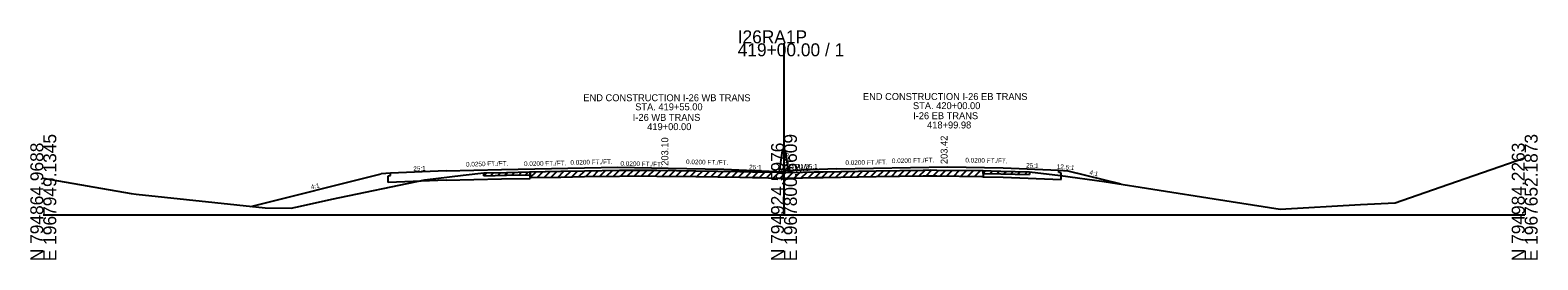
# Model space of a CAD drawing. Extents: x -44 to 4323, y -10 to 9601.
# Drawn here: x 997.2 to 1322.8, y 1490.3 to 1539.9 of the extents above; entities that cross this region are included whole.
import ezdxf

# ---------------------------------------------------------------- set-up
doc = ezdxf.new("R2010")
doc.units = 0
for name, color, linetype in [('1', 7, 'Continuous'), ('DateStamp', 7, 'Continuous'), ('NotForConst', 7, 'Continuous'), ('QCQA', 7, 'Continuous'), ('RD_SHT_Bndy', 7, 'Continuous'), ('RD_SHT_Iplotshp', 7, 'Continuous'), ('RD_SHT_TX', 7, 'Continuous'), ('RD_XS_ExGround', 7, 'Continuous'), ('RD_XS_MatchLine', 7, 'Continuous'), ('RD_XS_MedBWall', 7, 'Continuous'), ('RD_XS_Misc_Line', 7, 'Continuous'), ('RD_XS_Pave', 7, 'Continuous'), ('RD_XS_PaveShd', 7, 'Continuous'), ('RD_XS_TieSlope', 7, 'Continuous'), ('RD_XS_TX_Elev_PR', 7, 'Continuous'), ('RD_XS_TX_Profile', 7, 'Continuous'), ('RD_XS_TX_ShdSlope', 7, 'Continuous'), ('RD_XS_TX_Slope', 7, 'Continuous'), ('seal', 7, 'Continuous'), ('TR SN EXTRUDED PANEL SIGNS - GROUND MOUNTED', 7, 'Continuous')]:
    doc.layers.add(name, color=color, linetype=linetype)

msp = doc.modelspace()

# ---------------------------------------------------------------- linework, layer by layer
at = {"layer": 'DateStamp'}
msp.add_lwpolyline([(1000, 1507.96), (1018.98, 1504.64), (1020.04, 1504.48), (1047.96, 1501.5), (1053.55, 1501.46), (1055.55, 1501.88), (1062.32, 1503.37), (1082.4, 1507.55), (1090.69, 1508.57), (1095.19, 1509.08), (1100.04, 1509.19), (1105.01, 1509.29), (1111.79, 1509.44), (1116.92, 1509.54), (1124.49, 1509.64), (1128.57, 1509.7), (1132.56, 1509.64), (1140.92, 1509.53), (1150.43, 1509.38), (1153.17, 1509.33), (1154.46, 1509.3), (1158.82, 1509.21), (1160, 1509.2), (1161.53, 1509.18), (1166.5, 1509.3), (1167.16, 1509.31), (1168.45, 1509.33), (1179.9, 1509.52), (1190.09, 1509.69), (1191.7, 1509.71), (1193.03, 1509.7), (1202.72, 1509.58), (1206.86, 1509.48), (1213, 1509.34), (1219.72, 1508.48), (1229.13, 1507.25), (1252.93, 1503.5), (1267.19, 1501.27), (1284.55, 1502.23), (1292.04, 1502.64), (1301.71, 1505.98), (1320, 1512.35)], dxfattribs=at)
at = {"layer": 'NotForConst'}
for p, q in [((1095.19, 1508.46), (1095.83, 1509.1)), ((1096.69, 1508.49), (1097.33, 1509.13)), ((1098.19, 1508.52), (1098.83, 1509.16)), ((1099.69, 1508.56), (1100.33, 1509.19)), ((1101.19, 1508.59), (1101.83, 1509.23)), ((1102.69, 1508.62), (1103.33, 1509.26)), ((1104.19, 1508.65), (1104.83, 1509.29)), ((1105.19, 1508.05), (1106.47, 1509.32)), ((1106.69, 1508.08), (1107.97, 1509.36)), ((1108.19, 1508.11), (1109.47, 1509.39)), ((1109.69, 1508.14), (1110.97, 1509.42)), ((1111.19, 1508.18), (1112.47, 1509.45)), ((1112.69, 1508.21), (1113.97, 1509.48)), ((1114.19, 1508.24), (1115.47, 1509.51)), ((1115.69, 1508.27), (1116.97, 1509.54)), ((1117.19, 1508.3), (1118.46, 1509.56)), ((1118.69, 1508.32), (1119.96, 1509.58)), ((1120.19, 1508.34), (1121.46, 1509.6)), ((1121.69, 1508.36), (1122.96, 1509.62)), ((1123.19, 1508.38), (1124.46, 1509.64)), ((1124.69, 1508.4), (1125.96, 1509.66)), ((1126.19, 1508.42), (1127.46, 1509.68)), ((1127.69, 1508.44), (1128.95, 1509.69)), ((1129.19, 1508.44), (1130.43, 1509.67)), ((1130.69, 1508.42), (1131.93, 1509.65)), ((1132.19, 1508.4), (1133.43, 1509.63)), ((1133.69, 1508.38), (1134.93, 1509.61)), ((1135.19, 1508.36), (1136.43, 1509.59)), ((1136.69, 1508.34), (1137.93, 1509.57)), ((1138.2, 1508.32), (1139.43, 1509.55)), ((1139.7, 1508.3), (1140.93, 1509.53)), ((1141.2, 1508.28), (1142.43, 1509.51)), ((1142.7, 1508.25), (1143.93, 1509.48)), ((1144.2, 1508.23), (1145.43, 1509.46)), ((1145.7, 1508.2), (1146.93, 1509.43)), ((1147.2, 1508.18), (1148.43, 1509.41)), ((1148.7, 1508.16), (1149.93, 1509.39)), ((1150.2, 1508.13), (1151.43, 1509.36)), ((1151.7, 1508.11), (1152.93, 1509.34)), ((1153.2, 1508.08), (1154.42, 1509.31)), ((1154.7, 1508.05), (1155.92, 1509.27)), ((1156.2, 1508.02), (1157.42, 1509.24)), ((1157.7, 1507.99), (1158.92, 1509.21)), ((1159.2, 1507.96), (1160.43, 1509.19)), ((1160.7, 1507.94), (1161.94, 1509.19)), ((1162.2, 1507.94), (1163.48, 1509.22)), ((1163.7, 1507.98), (1164.98, 1509.26)), ((1165.2, 1508.01), (1166.48, 1509.3)), ((1166.7, 1508.05), (1167.97, 1509.32)), ((1168.2, 1508.08), (1169.47, 1509.35)), ((1169.7, 1508.1), (1170.97, 1509.37)), ((1171.2, 1508.13), (1172.47, 1509.4)), ((1172.7, 1508.15), (1173.97, 1509.42)), ((1174.2, 1508.17), (1175.47, 1509.45)), ((1175.7, 1508.2), (1176.97, 1509.47)), ((1177.2, 1508.22), (1178.47, 1509.49)), ((1178.7, 1508.25), (1179.97, 1509.52)), ((1180.2, 1508.27), (1181.47, 1509.54)), ((1181.7, 1508.3), (1182.97, 1509.57)), ((1183.2, 1508.32), (1184.47, 1509.59)), ((1184.7, 1508.35), (1185.97, 1509.62)), ((1186.2, 1508.37), (1187.47, 1509.64)), ((1187.7, 1508.4), (1188.97, 1509.67)), ((1189.2, 1508.42), (1190.47, 1509.69)), ((1190.7, 1508.45), (1191.96, 1509.71)), ((1192.2, 1508.46), (1193.44, 1509.69)), ((1193.7, 1508.44), (1194.93, 1509.68)), ((1195.2, 1508.42), (1196.43, 1509.66)), ((1196.7, 1508.4), (1197.93, 1509.64)), ((1198.2, 1508.39), (1199.43, 1509.62)), ((1199.7, 1508.37), (1200.93, 1509.6)), ((1201.2, 1508.35), (1202.43, 1509.58)), ((1203, 1508.95), (1203.61, 1509.56)), ((1204.5, 1508.91), (1205.11, 1509.52)), ((1206, 1508.88), (1206.61, 1509.49)), ((1207.5, 1508.84), (1208.11, 1509.45)), ((1209, 1508.81), (1209.61, 1509.42)), ((1210.5, 1508.77), (1211.11, 1509.38)), ((1212, 1508.74), (1212.61, 1509.35))]:
    msp.add_line(p, q, dxfattribs=at)
at = {"layer": 'QCQA'}
for p, q in [((1105.19, 1509.3), (1111.79, 1509.44)), ((1105.19, 1509.3), (1105.19, 1507.9)), ((1111.79, 1509.44), (1116.92, 1509.54)), ((1116.92, 1509.54), (1124.49, 1509.64)), ((1124.49, 1509.64), (1128.57, 1509.7)), ((1128.57, 1509.7), (1132.56, 1509.64)), ((1132.56, 1509.64), (1140.92, 1509.53)), ((1140.92, 1509.53), (1150.43, 1509.38)), ((1150.43, 1509.38), (1153.17, 1509.33)), ((1153.17, 1509.33), (1154.46, 1509.3)), ((1154.46, 1509.3), (1158.82, 1509.21)), ((1158.82, 1509.21), (1160, 1509.2)), ((1160, 1509.2), (1161.53, 1509.18)), ((1161.53, 1509.18), (1166.5, 1509.3)), ((1166.5, 1509.3), (1167.16, 1509.31)), ((1167.16, 1509.31), (1168.45, 1509.33)), ((1168.45, 1509.33), (1179.9, 1509.52)), ((1179.9, 1509.52), (1190.09, 1509.69)), ((1190.09, 1509.69), (1191.7, 1509.71)), ((1191.7, 1509.71), (1193.03, 1509.7)), ((1193.03, 1509.7), (1202.72, 1509.58)), ((1202.72, 1509.58), (1203, 1509.57)), ((1203, 1509.57), (1203, 1508.22))]:
    msp.add_line(p, q, dxfattribs=at)
at = {"layer": 'RD_SHT_Bndy'}
for p, q in [((1160, 1500), (1160, 1537.05)), ((1000, 1500), (1160, 1500)), ((1160, 1500), (1320, 1500))]:
    msp.add_line(p, q, dxfattribs=at)
at = {"layer": 'RD_SHT_Iplotshp'}
for p, q in [((1095.19, 1508.46), (1095.19, 1509.08)), ((1095.19, 1508.46), (1100.04, 1508.56)), ((1100.04, 1508.56), (1105.01, 1508.67)), ((1105.01, 1508.67), (1105.19, 1508.67)), ((1105.19, 1508.05), (1105.19, 1509.3)), ((1105.19, 1509.3), (1105.19, 1508.67)), ((1105.19, 1508.05), (1111.79, 1508.19)), ((1111.79, 1508.19), (1116.92, 1508.29)), ((1116.92, 1508.29), (1124.49, 1508.39)), ((1124.49, 1508.39), (1128.57, 1508.45)), ((1128.57, 1508.45), (1132.56, 1508.39)), ((1132.56, 1508.39), (1140.92, 1508.28)), ((1140.92, 1508.28), (1150.43, 1508.13)), ((1150.43, 1508.13), (1153.17, 1508.08)), ((1153.17, 1508.08), (1154.46, 1508.05)), ((1154.46, 1508.05), (1158.82, 1507.96)), ((1158.82, 1507.96), (1160, 1507.95)), ((1160, 1507.95), (1161.53, 1507.93)), ((1161.53, 1507.93), (1166.5, 1508.05)), ((1166.5, 1508.05), (1167.16, 1508.06)), ((1167.16, 1508.06), (1168.45, 1508.08)), ((1168.45, 1508.08), (1179.9, 1508.27)), ((1179.9, 1508.27), (1190.09, 1508.44)), ((1190.09, 1508.44), (1191.7, 1508.46)), ((1191.7, 1508.46), (1193.03, 1508.45)), ((1193.03, 1508.45), (1202.72, 1508.33)), ((1202.72, 1508.33), (1203, 1508.32)), ((1203, 1509.57), (1203, 1508.32)), ((1203, 1508.95), (1203, 1509.57)), ((1203, 1508.95), (1206.86, 1508.86)), ((1206.86, 1508.86), (1213, 1508.71)), ((1213, 1509.34), (1213, 1508.71))]:
    msp.add_line(p, q, dxfattribs=at)
at = {"layer": 'RD_XS_Misc_Line'}
for p, q in [((1074.5, 1508.46), (1075, 1508.48)), ((1074.5, 1506.98), (1074.5, 1508.46)), ((1075, 1508.48), (1075, 1509.04)), ((1203, 1508.22), (1207.33, 1508.14)), ((1207.33, 1508.14), (1219.84, 1507.64)), ((1219.34, 1509.14), (1219.34, 1509.7)), ((1219.84, 1509.12), (1219.34, 1509.14)), ((1219.84, 1507.64), (1219.84, 1509.12)), ((1087, 1507.48), (1074.5, 1506.98)), ((1087, 1507.48), (1099, 1507.78)), ((1099, 1507.78), (1105.19, 1507.9))]:
    msp.add_line(p, q, dxfattribs=at)
at = {"layer": 'RD_XS_Pave'}
for p, q in [((1044.82, 1501.83), (1073, 1508.88)), ((1221.34, 1509.54), (1232.76, 1506.68))]:
    msp.add_line(p, q, dxfattribs=at)
at = {"layer": 'RD_XS_PaveShd'}
for p, q in [((1075, 1509.04), (1073, 1508.88)), ((1219.34, 1509.7), (1221.34, 1509.54))]:
    msp.add_line(p, q, dxfattribs=at)
at = {"layer": 'RD_XS_TieSlope'}
msp.add_lwpolyline([(1160, 1509.34), (1160, 1509.49)], dxfattribs=at)
at = {"layer": 'RD_XS_TX_Elev_PR'}
for p, q in [((1087, 1509.52), (1075, 1509.04)), ((1147, 1509.86), (1160, 1509.34)), ((1171.33, 1509.94), (1160, 1509.49)), ((1207.33, 1510.18), (1219.34, 1509.7))]:
    msp.add_line(p, q, dxfattribs=at)
at = {"layer": 'RD_XS_TX_ShdSlope'}
for p, q in [((1159, 1509.36), (1159.67, 1513.84)), ((1159.67, 1513.99), (1160.33, 1513.99)), ((1159.67, 1513.84), (1159.67, 1513.99)), ((1161, 1509.51), (1160.33, 1513.99))]:
    msp.add_line(p, q, dxfattribs=at)
at = {"layer": 'RD_XS_TX_Slope'}
for p, q in [((1087, 1509.52), (1099, 1509.82)), ((1099, 1509.82), (1124.14, 1510.32)), ((1124.14, 1510.32), (1135, 1510.1)), ((1135, 1510.1), (1147, 1509.86)), ((1171.33, 1509.94), (1195.33, 1510.42)), ((1195.33, 1510.42), (1207.33, 1510.18))]:
    msp.add_line(p, q, dxfattribs=at)

# ---------------------------------------------------------------- texts
at = {"layer": '1'}
for s, p in [('I-26 WB TRANS', (1127.33, 1520.31)), ('I-26 EB TRANS', (1187.89, 1520.67)), ('419+00.00', (1130.45, 1518.31)), ('418+99.98', (1190.91, 1518.67))]:
    msp.add_text(s, height=1.5, dxfattribs=at).set_placement(p)
at = {"layer": 'RD_SHT_Bndy'}
for s, p in [('I26RA1P', (1150, 1537.05)), ('419+00.00 / 1', (1150, 1534.25))]:
    msp.add_text(s, height=2.8, dxfattribs=at).set_placement(p)
for s, p in [('N 794864.9688', (1000, 1490)), ('E 1967949.1345', (1002.8, 1490)), ('N 794924.5976', (1160, 1490)), ('E 1967800.6609', (1162.8, 1490)), ('N 794984.2263', (1320, 1490)), ('E 1967652.1873', (1322.8, 1490))]:
    msp.add_text(s, height=2.8, rotation=90, dxfattribs=at).set_placement(p)
at = {"layer": 'RD_SHT_TX'}
msp.add_text('202.20', height=1, rotation=90, dxfattribs=at).set_placement((1161, 1509.2))
at = {"layer": 'RD_XS_ExGround'}
for rotation, p in [(357.7097, (1212.29, 1510.23)), (2.2906, (1079.94, 1509.48)), (357.7094, (1152.46, 1509.85)), (2.2903, (1164.6, 1509.92))]:
    msp.add_text('25:1', height=1, rotation=rotation, dxfattribs=at).set_placement(p)
at = {"layer": 'RD_XS_MatchLine'}
for s, p in [('END CONSTRUCTION I-26 WB TRANS', (1116.66, 1524.55)), ('END CONSTRUCTION I-26 EB TRANS', (1177.04, 1524.81)), ('STA. 420+00.00', (1187.86, 1522.84)), ('STA. 419+55.00', (1127.86, 1522.59))]:
    msp.add_text(s, height=1.5, dxfattribs=at).set_placement(p)
at = {"layer": 'RD_XS_MedBWall'}
msp.add_text('12.5:1', height=1, rotation=355.4267, dxfattribs=at).set_placement((1218.88, 1509.98))
at = {"layer": 'RD_XS_TX_Profile'}
for s, p in [('WBW', (1159, 1509.36)), ('EBW', (1161, 1509.51))]:
    msp.add_text(s, height=1.5, dxfattribs=at).set_placement(p)
at = {"layer": 'seal'}
for s, p in [(' 203.10', (1135, 1510.06)), (' 203.42', (1195.33, 1510.42))]:
    msp.add_text(s, height=1.5, rotation=90, dxfattribs=at).set_placement(p)
at = {"layer": 'TR SN EXTRUDED PANEL SIGNS - GROUND MOUNTED'}
for s, rotation, p in [('0.0250 FT./FT.', 1.4321, (1091.31, 1510.43)), ('0.0200 FT./FT.', 1.1458, (1103.84, 1510.54)), ('0.0200 FT./FT.', 1.1458, (1113.86, 1510.83)), ('0.0200 FT./FT.', 358.8542, (1124.66, 1510.62)), ('0.0200 FT./FT.', 358.8542, (1138.83, 1510.98)), ('0.0200 FT./FT.', 1.1404, (1173.27, 1510.77)), ('0.0200 FT./FT.', 1.1404, (1183.31, 1511.18)), ('0.0200 FT./FT.', 358.8495, (1199.16, 1511.34)), ('4:1', 345.9638, (1225.89, 1508.77)), ('4:1', 14.0362, (1057.91, 1505.49))]:
    msp.add_text(s, height=1, rotation=rotation, dxfattribs=at).set_placement(p)

doc.saveas('drawing.dxf')
